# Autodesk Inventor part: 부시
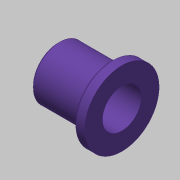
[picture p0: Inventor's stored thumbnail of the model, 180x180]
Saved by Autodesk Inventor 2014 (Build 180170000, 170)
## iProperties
Created: 2019-10
Part Number: 부시
Material: 강철, 연강
Document SubType Name: Modeling
Designer: mduedu
Density: 1 g/cm^3
Appearance: 보라색
Author: mduedu
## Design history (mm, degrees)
sketch "스케치1"
  geometry: L1 (0, 0)-(-18, 0); L2 (0, -5.5)-(0, -10.5); L3 (0, -10.5)-(-3, -10.5); L4 (-3, -10.5)-(-3, -7.5); L5 (-3, -7.5)-(-18, -7.5); L6 (-18, -7.5)-(-18, -5.5); L7 (-18, -5.5)-(0, -5.5)
  constraints: 14 end point, 3 parallel, 2 horizontal, 2 perpendicular, 2 vertical alignment
  dimensions: "d0" = 18 distance of L1.start L1.end; "d1" = 11 diameter of L7 L1; "d2" = 15 diameter of L5 L1; "d3" = 21 diameter of L3 L1; "d4" = 3 distance of L2.end L3.end
revolve "회전1" sketch "스케치1" stored, may be unused: angle "d5" = 90 deg
chamfer "모따기1" distance "d6" = 0.5; stored, may be unused: second distance "d7" = 2, angle "d8" = 45 deg
chamfer "모따기2" distance "d9" = 0.5; stored, may be unused: second distance "d10" = 2, angle "d11" = 45 deg
node "솔리드1"
